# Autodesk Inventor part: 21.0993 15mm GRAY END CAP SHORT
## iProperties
Created: 2007-01
Part Number: 21.0993 15mm GRAY END CAP SHORT
Document SubType Name: Modeling
Designer: Andy Moles
Material: ABS Plastic
Density: 1.06 g/cm^3
Mass: 0.520799 g
Surface Area: 10.279 cm^2
Volume: 0.49132 cm^3
Author: Andy Moles
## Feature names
1. Revolution1
